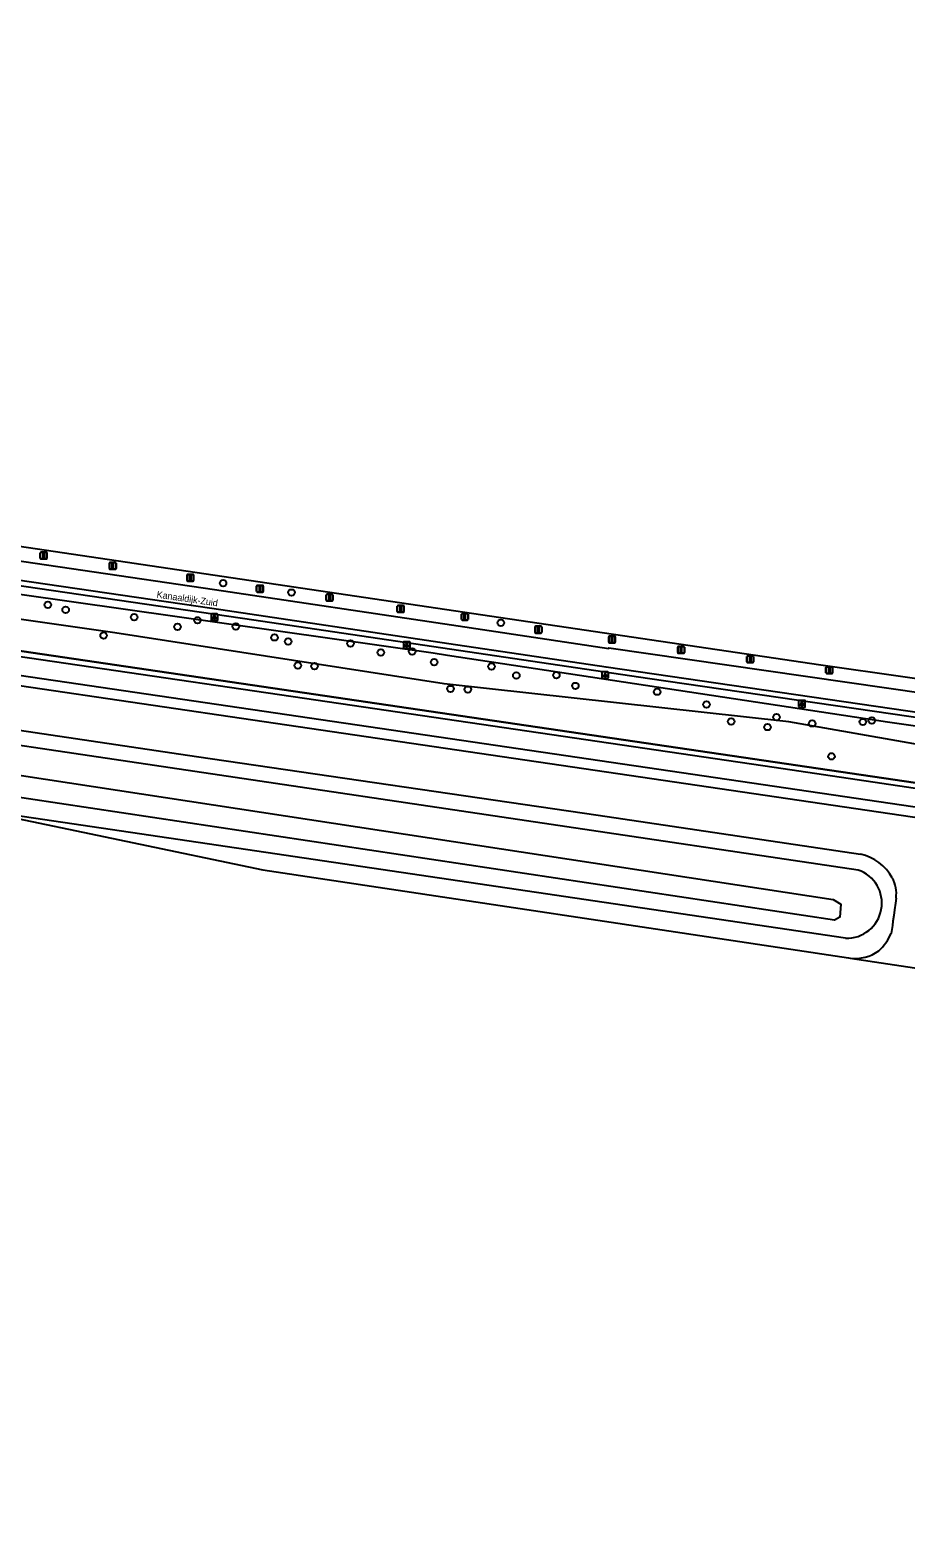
# Model space of a CAD drawing. Extents: x 163046 to 165074, y 382019 to 382874.
# Drawn here: x 163631.7 to 163762.7, y 382627.9 to 382853.5 of the extents above; entities that cross this region are included whole.
import ezdxf

# ---------------------------------------------------------------- set-up
doc = ezdxf.new("R2010")
doc.units = 0
for name, color, linetype in [('IMGEO_Afsluitpaal', 7, 'Continuous'), ('IMGEO_Boom', 7, 'Continuous'), ('IMGEO_Erf', 7, 'Continuous'), ('IMGEO_Fietspad_gesloten', 7, 'Continuous'), ('IMGEO_Groenvoorziening', 7, 'Continuous'), ('IMGEO_Hek', 7, 'Continuous'), ('IMGEO_Lichtpunt', 7, 'Continuous'), ('IMGEO_Openbare_ruimte_label', 7, 'Continuous'), ('IMGEO_Rijbaan_lokaal_gesloten', 7, 'Continuous'), ('IMGEO_Rijbaan_lokaal_halfverhard', 7, 'Continuous'), ('IMGEO_Waterloop', 7, 'Continuous')]:
    doc.layers.add(name, color=color, linetype=linetype)

msp = doc.modelspace()

# ---------------------------------------------------------------- linework, layer by layer
at = {"layer": 'IMGEO_Afsluitpaal'}
for p, q in [((163633.35, 382775.38), (163634.14, 382775.38)), ((163634.14, 382775.38), (163633.35, 382775.38)), ((163633.25, 382774.48), (163633.25, 382775.28)), ((163633.25, 382775.28), (163633.25, 382774.48)), ((163634.14, 382774.38), (163633.35, 382774.38)), ((163633.35, 382774.38), (163634.14, 382774.38)), ((163634.24, 382775.28), (163634.24, 382774.48)), ((163634.24, 382774.48), (163634.24, 382775.28)), ((163643.59, 382772.93), (163643.59, 382773.73)), ((163643.59, 382773.73), (163643.59, 382772.93)), ((163643.69, 382773.83), (163644.48, 382773.83)), ((163644.48, 382773.83), (163643.69, 382773.83)), ((163644.58, 382773.73), (163644.58, 382772.93)), ((163644.58, 382772.93), (163644.58, 382773.73)), ((163644.48, 382772.83), (163643.69, 382772.83)), ((163643.69, 382772.83), (163644.48, 382772.83)), ((163655.19, 382771.16), (163655.19, 382771.96)), ((163655.19, 382771.96), (163655.19, 382771.16)), ((163655.29, 382772.06), (163656.07, 382772.06)), ((163656.07, 382772.06), (163655.29, 382772.06)), ((163656.07, 382771.06), (163655.29, 382771.06)), ((163655.29, 382771.06), (163656.07, 382771.06)), ((163656.17, 382771.96), (163656.17, 382771.16)), ((163656.17, 382771.16), (163656.17, 382771.96)), ((163665.6, 382769.53), (163665.6, 382770.33)), ((163665.6, 382770.33), (163665.6, 382769.53)), ((163665.7, 382770.43), (163666.49, 382770.43)), ((163666.49, 382770.43), (163665.7, 382770.43)), ((163666.49, 382769.43), (163665.7, 382769.43)), ((163665.7, 382769.43), (163666.49, 382769.43)), ((163666.59, 382770.33), (163666.59, 382769.53)), ((163666.59, 382769.53), (163666.59, 382770.33)), ((163676.01, 382768.2), (163676.01, 382769)), ((163676.01, 382769), (163676.01, 382768.2)), ((163676.11, 382769.1), (163676.9, 382769.1)), ((163676.9, 382769.1), (163676.11, 382769.1)), ((163677, 382769), (163677, 382768.2)), ((163677, 382768.2), (163677, 382769)), ((163676.9, 382768.1), (163676.11, 382768.1)), ((163676.11, 382768.1), (163676.9, 382768.1)), ((163686.64, 382766.51), (163686.64, 382767.31)), ((163686.64, 382767.31), (163686.64, 382766.51)), ((163686.74, 382767.41), (163687.53, 382767.41)), ((163687.53, 382767.41), (163686.74, 382767.41)), ((163687.53, 382766.41), (163686.74, 382766.41)), ((163686.74, 382766.41), (163687.53, 382766.41)), ((163687.63, 382767.31), (163687.63, 382766.51)), ((163687.63, 382766.51), (163687.63, 382767.31)), ((163696.24, 382765.32), (163696.24, 382766.12)), ((163696.24, 382766.12), (163696.24, 382765.32)), ((163696.34, 382766.22), (163697.13, 382766.22)), ((163697.13, 382766.22), (163696.34, 382766.22)), ((163697.13, 382765.22), (163696.34, 382765.22)), ((163696.34, 382765.22), (163697.13, 382765.22)), ((163697.23, 382766.12), (163697.23, 382765.32)), ((163697.23, 382765.32), (163697.23, 382766.12)), ((163707.24, 382763.4), (163707.24, 382764.2)), ((163707.24, 382764.2), (163707.24, 382763.4)), ((163707.34, 382764.3), (163708.13, 382764.3)), ((163708.13, 382764.3), (163707.34, 382764.3)), ((163708.23, 382764.2), (163708.23, 382763.4)), ((163708.23, 382763.4), (163708.23, 382764.2)), ((163708.13, 382763.3), (163707.34, 382763.3)), ((163707.34, 382763.3), (163708.13, 382763.3)), ((163718.25, 382761.93), (163718.25, 382762.73)), ((163718.25, 382762.73), (163718.25, 382761.93)), ((163718.35, 382762.83), (163719.14, 382762.83)), ((163719.14, 382762.83), (163718.35, 382762.83)), ((163719.14, 382761.83), (163718.35, 382761.83)), ((163718.35, 382761.83), (163719.14, 382761.83)), ((163719.24, 382762.73), (163719.24, 382761.93)), ((163719.24, 382761.93), (163719.24, 382762.73)), ((163728.58, 382760.38), (163728.58, 382761.18)), ((163728.58, 382761.18), (163728.58, 382760.38)), ((163728.68, 382761.28), (163729.47, 382761.28)), ((163729.47, 382761.28), (163728.68, 382761.28)), ((163729.47, 382760.28), (163728.68, 382760.28)), ((163728.68, 382760.28), (163729.47, 382760.28)), ((163729.57, 382761.18), (163729.57, 382760.38)), ((163729.57, 382760.38), (163729.57, 382761.18)), ((163738.92, 382758.97), (163738.92, 382759.77)), ((163738.92, 382759.77), (163738.92, 382758.97)), ((163739.02, 382759.87), (163739.81, 382759.87)), ((163739.81, 382759.87), (163739.02, 382759.87)), ((163739.91, 382759.77), (163739.91, 382758.97)), ((163739.91, 382758.97), (163739.91, 382759.77)), ((163739.81, 382758.87), (163739.02, 382758.87)), ((163739.02, 382758.87), (163739.81, 382758.87)), ((163750.74, 382757.35), (163750.74, 382758.15)), ((163750.74, 382758.15), (163750.74, 382757.35)), ((163750.84, 382758.25), (163751.63, 382758.25)), ((163751.63, 382758.25), (163750.84, 382758.25)), ((163751.73, 382758.15), (163751.73, 382757.35)), ((163751.73, 382757.35), (163751.73, 382758.15)), ((163751.63, 382757.25), (163750.84, 382757.25)), ((163750.84, 382757.25), (163751.63, 382757.25))]:
    msp.add_line(p, q, dxfattribs=at)
for points in [[(163633.67, 382775.26), (163633.82, 382775.26), (163633.82, 382774.51), (163633.67, 382774.51), (163633.67, 382775.26)], [(163644.01, 382773.71), (163644.16, 382773.71), (163644.16, 382772.96), (163644.01, 382772.96), (163644.01, 382773.71)], [(163655.6, 382771.93), (163655.76, 382771.93), (163655.76, 382771.18), (163655.6, 382771.18), (163655.6, 382771.93)], [(163666.02, 382770.31), (163666.17, 382770.31), (163666.17, 382769.56), (163666.02, 382769.56), (163666.02, 382770.31)], [(163676.43, 382768.98), (163676.58, 382768.98), (163676.58, 382768.23), (163676.43, 382768.23), (163676.43, 382768.98)], [(163687.06, 382767.28), (163687.21, 382767.28), (163687.21, 382766.53), (163687.06, 382766.53), (163687.06, 382767.28)], [(163696.66, 382766.1), (163696.81, 382766.1), (163696.81, 382765.35), (163696.66, 382765.35), (163696.66, 382766.1)], [(163707.66, 382764.18), (163707.81, 382764.18), (163707.81, 382763.43), (163707.66, 382763.43), (163707.66, 382764.18)], [(163718.67, 382762.7), (163718.82, 382762.7), (163718.82, 382761.95), (163718.67, 382761.95), (163718.67, 382762.7)], [(163729, 382761.15), (163729.15, 382761.15), (163729.15, 382760.4), (163729, 382760.4), (163729, 382761.15)], [(163739.34, 382759.75), (163739.49, 382759.75), (163739.49, 382759), (163739.34, 382759), (163739.34, 382759.75)], [(163751.16, 382758.12), (163751.31, 382758.12), (163751.31, 382757.37), (163751.16, 382757.37), (163751.16, 382758.12)]]:
    msp.add_lwpolyline(points, dxfattribs=at)
for centre, start, end in [((163633.35, 382775.28), 90, 180), ((163633.35, 382775.28), 90, 180), ((163634.14, 382775.28), 0, 90), ((163634.14, 382775.28), 360, 90), ((163633.35, 382774.48), 180, 270), ((163633.35, 382774.48), 180, 270), ((163634.14, 382774.48), 270, 0), ((163634.14, 382774.48), 270, 0), ((163643.69, 382773.73), 90, 180), ((163643.69, 382773.73), 90, 180), ((163644.48, 382773.73), 0, 90), ((163644.48, 382773.73), 360, 90), ((163643.69, 382772.93), 180, 270), ((163643.69, 382772.93), 180, 270), ((163644.48, 382772.93), 270, 0), ((163644.48, 382772.93), 270, 0), ((163655.29, 382771.96), 90, 180), ((163655.29, 382771.96), 90, 180), ((163655.29, 382771.16), 180, 270), ((163655.29, 382771.16), 180, 270), ((163656.07, 382771.96), 0, 90), ((163656.07, 382771.96), 360, 90), ((163656.07, 382771.16), 270, 0), ((163656.07, 382771.16), 270, 0), ((163665.7, 382770.33), 90, 180), ((163665.7, 382770.33), 90, 180), ((163665.7, 382769.53), 180, 270), ((163665.7, 382769.53), 180, 270), ((163666.49, 382770.33), 0, 90), ((163666.49, 382770.33), 360, 90), ((163666.49, 382769.53), 270, 0), ((163666.49, 382769.53), 270, 0), ((163676.11, 382769), 90, 180), ((163676.11, 382769), 90, 180), ((163676.9, 382769), 0, 90), ((163676.9, 382769), 360, 90), ((163676.11, 382768.2), 180, 270), ((163676.11, 382768.2), 180, 270), ((163676.9, 382768.2), 270, 0), ((163676.9, 382768.2), 270, 0), ((163686.74, 382767.31), 90, 180), ((163686.74, 382767.31), 90, 180), ((163686.74, 382766.51), 180, 270), ((163686.74, 382766.51), 180, 270), ((163687.53, 382767.31), 0, 90), ((163687.53, 382767.31), 360, 90), ((163687.53, 382766.51), 270, 0), ((163687.53, 382766.51), 270, 0), ((163696.34, 382766.12), 90, 180), ((163696.34, 382766.12), 90, 180), ((163696.34, 382765.32), 180, 270), ((163696.34, 382765.32), 180, 270), ((163697.13, 382766.12), 0, 90), ((163697.13, 382766.12), 360, 90), ((163697.13, 382765.32), 270, 0), ((163697.13, 382765.32), 270, 0), ((163707.34, 382764.2), 90, 180), ((163707.34, 382764.2), 90, 180), ((163708.13, 382764.2), 0, 90), ((163708.13, 382764.2), 360, 90), ((163707.34, 382763.4), 180, 270), ((163707.34, 382763.4), 180, 270), ((163708.13, 382763.4), 270, 0), ((163708.13, 382763.4), 270, 0), ((163718.35, 382762.73), 90, 180), ((163718.35, 382762.73), 90, 180), ((163718.35, 382761.93), 180, 270), ((163718.35, 382761.93), 180, 270), ((163719.14, 382762.73), 0, 90), ((163719.14, 382762.73), 360, 90), ((163719.14, 382761.93), 270, 0), ((163719.14, 382761.93), 270, 0), ((163728.68, 382761.18), 90, 180), ((163728.68, 382761.18), 90, 180), ((163728.68, 382760.38), 180, 270), ((163728.68, 382760.38), 180, 270), ((163729.47, 382761.18), 0, 90), ((163729.47, 382761.18), 360, 90), ((163729.47, 382760.38), 270, 0), ((163729.47, 382760.38), 270, 0), ((163739.02, 382759.77), 90, 180), ((163739.02, 382759.77), 90, 180), ((163739.81, 382759.77), 0, 90), ((163739.81, 382759.77), 360, 90), ((163739.02, 382758.97), 180, 270), ((163739.02, 382758.97), 180, 270), ((163739.81, 382758.97), 270, 0), ((163739.81, 382758.97), 270, 0), ((163750.84, 382758.15), 90, 180), ((163750.84, 382758.15), 90, 180), ((163750.84, 382757.35), 180, 270), ((163750.84, 382757.35), 180, 270), ((163751.63, 382758.15), 0, 90), ((163751.63, 382758.15), 360, 90), ((163751.63, 382757.35), 270, 0), ((163751.63, 382757.35), 270, 0)]:
    msp.add_arc(centre, 0.1, start, end, dxfattribs=at)
at = {"layer": 'IMGEO_Boom'}
for centre in [(163660.58, 382770.77), (163670.83, 382769.34), (163634.37, 382767.52), (163637.04, 382766.76), (163647.27, 382765.67), (163653.78, 382764.22), (163656.75, 382765.2), (163662.49, 382764.27), (163702.12, 382764.82), (163642.72, 382762.93), (163668.26, 382762.65), (163670.33, 382762.04), (163679.63, 382761.73), (163684.18, 382760.39), (163688.87, 382760.53), (163671.77, 382758.43), (163674.25, 382758.35), (163692.14, 382758.93), (163700.73, 382758.28), (163704.44, 382756.94), (163710.43, 382757), (163694.61, 382754.93), (163697.2, 382754.83), (163713.27, 382755.38), (163725.5, 382754.52), (163732.89, 382752.62), (163736.56, 382750.05), (163743.36, 382750.71), (163757.61, 382750.2), (163742, 382749.23), (163748.69, 382749.78), (163756.25, 382749.99), (163751.58, 382744.85)]:
    msp.add_circle(centre, 0.489, dxfattribs=at)
at = {"layer": 'IMGEO_Erf'}
for points in [[(163551.71, 382756.34), (163551.82, 382757.15), (163552.77, 382757.02), (163552.78, 382757.12), (163555.08, 382756.83), (163555.19, 382757.61), (163606.71, 382750), (163755.55, 382727.85)], [(163753.68, 382717.65), (163616.32, 382737.96), (163609.51, 382732.91), (163594.68, 382735.09), (163589.61, 382741.91), (163553.67, 382747.12), (163553.28, 382747.47), (163553.16, 382746.69)], [(163589.84, 382629.98), (163598.25, 382663.73), (163605.6, 382662.09), (163616.25, 382704.79), (163625.48, 382736.46), (163666.55, 382727.85), (163754.11, 382714.7), (163754.37, 382714.66)]]:
    msp.add_lwpolyline(points, dxfattribs=at)
msp.add_arc((163753.87, 382722.88), 5.24, 267.9484, 71.35, dxfattribs=at)
at = {"layer": 'IMGEO_Fietspad_gesloten'}
for points in [[(163262.2, 382833.43), (163314.79, 382823.48), (163323.12, 382821.97), (163364.34, 382814.88), (163364.32, 382814.73), (163391.13, 382810.02), (163404.12, 382807.82), (163422.79, 382804.65), (163452.38, 382800.08), (163452.39, 382800.23), (163481.75, 382795.75), (163600.16, 382778.49), (163659.31, 382769.79), (163694.75, 382764.5), (163718.27, 382760.99), (163718.28, 382761.09), (163777.46, 382752.55), (163894.24, 382735.48), (163935.71, 382729.35)], [(164290.62, 382661.73), (164274.25, 382664.12), (164260.42, 382666.24), (164243.89, 382668.69), (164144.23, 382683.65), (164123, 382686.71), (164101.01, 382689.99), (164076.37, 382693.78), (164055.27, 382696.95), (164027.35, 382701.08), (164001.81, 382704.9), (163972.99, 382709.21), (163941.3, 382713.95), (163899.36, 382720.17), (163864.59, 382725.29), (163853.75, 382726.93), (163828.34, 382730.66), (163782.57, 382737.3), (163742.98, 382743.16), (163672.74, 382753.5), (163608.81, 382762.9), (163587.4, 382766.11), (163537.53, 382773.31), (163534.17, 382773.83)], [(163557.09, 382767.74), (163843.81, 382725.57)]]:
    msp.add_lwpolyline(points, dxfattribs=at)
at = {"layer": 'IMGEO_Groenvoorziening'}
msp.add_lwpolyline([(163359.37, 382797.83), (163374.85, 382798.03), (163401.89, 382794.15), (163410.94, 382792.85), (163500, 382779.47), (163535.41, 382774.6), (163550.62, 382772.33), (163693.06, 382751.36), (163828.8, 382731.36), (163846.1, 382728.88), (163873.33, 382724.84), (163916.5, 382718.52), (163943.51, 382714.37), (163981.6, 382708.67), (164080.42, 382694.02), (164103.91, 382690.52), (164197.42, 382676.27), (164217.65, 382673.07), (164282.56, 382663.33), (164518.36, 382627.93)], dxfattribs=at)
at = {"layer": 'IMGEO_Hek'}
for points in [[(163693.06, 382751.36), (163550.62, 382772.33), (163535.41, 382774.6)], [(163981.6, 382708.67), (163943.51, 382714.37), (163916.5, 382718.52), (163873.33, 382724.84), (163846.1, 382728.88), (163828.8, 382731.36), (163693.06, 382751.36)]]:
    msp.add_lwpolyline(points, dxfattribs=at)
at = {"layer": 'IMGEO_Lichtpunt'}
for p, q in [((163658.78, 382766.05), (163658.78, 382765.25)), ((163658.78, 382766.05), (163658.78, 382765.25)), ((163659.68, 382766.15), (163658.88, 382766.15)), ((163659.68, 382766.15), (163658.88, 382766.15)), ((163658.88, 382765.15), (163659.68, 382765.15)), ((163658.88, 382765.15), (163659.68, 382765.15)), ((163659.78, 382765.25), (163659.78, 382766.05)), ((163659.78, 382765.25), (163659.78, 382766.05)), ((163687.56, 382761.89), (163687.56, 382761.09)), ((163687.56, 382761.89), (163687.56, 382761.09)), ((163688.46, 382761.99), (163687.65, 382761.99)), ((163688.46, 382761.99), (163687.65, 382761.99)), ((163688.56, 382761.09), (163688.56, 382761.89)), ((163688.56, 382761.09), (163688.56, 382761.89)), ((163687.65, 382760.99), (163688.46, 382760.99)), ((163687.65, 382760.99), (163688.46, 382760.99)), ((163717.23, 382757.4), (163717.23, 382756.59)), ((163717.23, 382757.4), (163717.23, 382756.59)), ((163718.13, 382757.49), (163717.33, 382757.49)), ((163718.13, 382757.49), (163717.33, 382757.49)), ((163718.23, 382756.59), (163718.23, 382757.4)), ((163718.23, 382756.59), (163718.23, 382757.4)), ((163717.33, 382756.49), (163718.13, 382756.49)), ((163717.33, 382756.49), (163718.13, 382756.49)), ((163746.65, 382753.12), (163746.65, 382752.31)), ((163746.65, 382753.12), (163746.65, 382752.31)), ((163747.55, 382753.22), (163746.74, 382753.22)), ((163747.55, 382753.22), (163746.74, 382753.22)), ((163747.65, 382752.31), (163747.65, 382753.12)), ((163747.65, 382752.31), (163747.65, 382753.12)), ((163746.74, 382752.22), (163747.55, 382752.22)), ((163746.74, 382752.22), (163747.55, 382752.22))]:
    msp.add_line(p, q, dxfattribs=at)
for points in [[(163659.16, 382765.72), (163659.2, 382765.69), (163659.01, 382765.43), (163658.97, 382765.45), (163659.16, 382765.72)], [(163659.26, 382765.67), (163659.31, 382765.67), (163659.31, 382765.35), (163659.26, 382765.35), (163659.26, 382765.67)], [(163659.37, 382765.69), (163659.41, 382765.72), (163659.59, 382765.45), (163659.56, 382765.43), (163659.37, 382765.69)], [(163687.93, 382761.56), (163687.97, 382761.53), (163687.78, 382761.27), (163687.75, 382761.29), (163687.93, 382761.56)], [(163688.03, 382761.51), (163688.08, 382761.51), (163688.08, 382761.19), (163688.03, 382761.19), (163688.03, 382761.51)], [(163688.14, 382761.53), (163688.18, 382761.56), (163688.37, 382761.29), (163688.33, 382761.27), (163688.14, 382761.53)], [(163717.61, 382757.06), (163717.64, 382757.03), (163717.46, 382756.77), (163717.42, 382756.8), (163717.61, 382757.06)], [(163717.71, 382757.01), (163717.76, 382757.01), (163717.76, 382756.69), (163717.71, 382756.69), (163717.71, 382757.01)], [(163717.82, 382757.03), (163717.86, 382757.06), (163718.04, 382756.8), (163718, 382756.77), (163717.82, 382757.03)], [(163747.02, 382752.78), (163747.06, 382752.76), (163746.87, 382752.49), (163746.84, 382752.52), (163747.02, 382752.78)], [(163747.23, 382752.76), (163747.27, 382752.78), (163747.46, 382752.52), (163747.42, 382752.49), (163747.23, 382752.76)], [(163747.12, 382752.74), (163747.17, 382752.74), (163747.17, 382752.41), (163747.12, 382752.41), (163747.12, 382752.74)]]:
    msp.add_lwpolyline(points, dxfattribs=at)
for centre in [(163659.28, 382765.85), (163688.06, 382761.69), (163717.73, 382757.19), (163747.15, 382752.92)]:
    msp.add_circle(centre, 0.0994, dxfattribs=at)
for centre, start, end in [((163658.88, 382766.05), 90, 180), ((163658.88, 382766.05), 90, 180), ((163658.88, 382765.25), 180, 270), ((163658.88, 382765.25), 180, 270), ((163659.68, 382766.05), 0, 90), ((163659.68, 382766.05), 0, 90), ((163659.68, 382765.25), 270, 0), ((163659.68, 382765.25), 270, 360), ((163687.65, 382761.89), 90, 180), ((163687.65, 382761.89), 90, 180), ((163688.46, 382761.89), 0, 90), ((163688.46, 382761.89), 0, 90), ((163687.65, 382761.09), 180, 270), ((163687.65, 382761.09), 180, 270), ((163688.46, 382761.09), 270, 0), ((163688.46, 382761.09), 270, 360), ((163717.33, 382757.4), 90, 180), ((163717.33, 382757.4), 90, 180), ((163718.13, 382757.4), 0, 90), ((163718.13, 382757.4), 0, 90), ((163717.33, 382756.59), 180, 270), ((163717.33, 382756.59), 180, 270), ((163718.13, 382756.59), 270, 0), ((163718.13, 382756.59), 270, 360), ((163746.74, 382753.12), 90, 180), ((163746.74, 382753.12), 90, 180), ((163747.55, 382753.12), 0, 90), ((163747.55, 382753.12), 0, 90), ((163746.74, 382752.31), 180, 270), ((163746.74, 382752.31), 180, 270), ((163747.55, 382752.31), 270, 0), ((163747.55, 382752.31), 270, 360)]:
    msp.add_arc(centre, 0.0946, start, end, dxfattribs=at)
at = {"layer": 'IMGEO_Rijbaan_lokaal_gesloten'}
for points in [[(163843.6, 382723.98), (163831.84, 382725.71), (163666.72, 382750), (163556.9, 382766.15)], [(163555.64, 382759.8), (163592.57, 382754.34), (163656.59, 382744.84), (163716.68, 382736.05), (163755.9, 382730.2)], [(163761.24, 382723.64), (163761.15, 382722.89), (163761.01, 382721.91), (163760.89, 382721.05), (163760.77, 382720.2), (163760.7, 382719.56), (163760.49, 382718.36)], [(163754.37, 382714.66), (163779.91, 382710.83)]]:
    msp.add_lwpolyline(points, dxfattribs=at)
for centre, radius, start, end in [((163754.55, 382723.46), 6.88, 27.6255, 78.7043), ((163756.67, 382724.31), 4.61, 351.7137, 30.4658), ((163753.32, 382721.49), 7.83, 312.818, 336.3817), ((163755.13, 382720.59), 5.98, 262.7775, 305.9827)]:
    msp.add_arc(centre, radius, start, end, dxfattribs=at)
at = {"layer": 'IMGEO_Rijbaan_lokaal_halfverhard'}
for points in [[(163935.2, 382726.45), (163865.22, 382736.76), (163777.02, 382749.58), (163717.86, 382758.17), (163694.37, 382761.68), (163658.89, 382766.97), (163481.33, 382792.88), (163422.35, 382801.94), (163403.68, 382805.1), (163390.65, 382807.22), (163363.84, 382811.92), (163322.62, 382819.12), (163314.27, 382820.6), (163290.92, 382824.68), (163261.84, 382830.05)], [(163322.47, 382818.43), (163367.47, 382810.55), (163392.06, 382806.33), (163416.38, 382802.09), (163437.86, 382798.77), (163477.86, 382792.74), (163535.08, 382784.39), (163586.49, 382776.8), (163665.19, 382765.27), (163724.04, 382756.55), (163797.09, 382745.94), (163942.52, 382724.63), (163982.95, 382718.82), (164038.68, 382710.5), (164106.21, 382700.45), (164167.93, 382691.09), (164227.93, 382681.9), (164243.96, 382679.59)]]:
    msp.add_lwpolyline(points, dxfattribs=at)
at = {"layer": 'IMGEO_Waterloop'}
for points in [[(163181.62, 382853.49), (163197.03, 382850.28), (163305.26, 382829.6), (163305.57, 382830.01), (163310.04, 382829.2), (163310.24, 382828.46), (163351.91, 382819.96), (163378.29, 382814.85), (163404.52, 382810.31), (163423.67, 382806.99), (163441.72, 382804), (163484.72, 382798.05), (163500, 382795.74), (163550.36, 382788.13), (163695.04, 382766.67), (163750, 382758.53), (163787.83, 382753.17), (163808.82, 382750), (163842.64, 382744.9), (163893.44, 382737.78), (163957.08, 382728.48), (163984.26, 382724.67)], [(163960.72, 382718.96), (163901.57, 382725.6), (163891.58, 382726.84), (163814.14, 382738.31), (163792.78, 382741.61), (163745.19, 382750), (163693.63, 382755.7), (163644.4, 382763.31), (163599.03, 382769.82), (163550.48, 382777.74), (163531.31, 382780.73), (163500, 382785.31), (163403.56, 382799.39), (163402.77, 382799.54), (163335.61, 382812.21), (163322.88, 382814.5)], [(163337.61, 382814.84), (163359.3, 382810.82), (163403.34, 382803.03), (163422.96, 382799.57), (163500, 382787.56), (163548.66, 382779.98), (163558.31, 382778.65), (163599.59, 382773.47), (163692, 382760.32), (163694.14, 382759.99), (163759.96, 382750), (163780.57, 382747.06), (163793.38, 382745.36), (163843.66, 382737.95), (163892.47, 382731.14), (163941.47, 382723.93), (163961.29, 382721.23)], [(163550.24, 382753.72), (163551.31, 382753.63), (163551.87, 382753.58), (163554.57, 382753.35), (163556.34, 382753.2), (163562.84, 382752.3), (163751.82, 382723.43), (163752.98, 382722.72), (163752.82, 382720.79), (163752.03, 382720.32), (163612.9, 382741.27), (163607.89, 382736.86), (163595.91, 382738.22), (163590.56, 382745.01), (163555.74, 382750.53)]]:
    msp.add_lwpolyline(points, dxfattribs=at)

# ---------------------------------------------------------------- texts
at = {"layer": 'IMGEO_Openbare_ruimte_label'}
msp.add_text('Kanaaldijk-Zuid', height=1, rotation=351.6591, dxfattribs=at).set_placement((163650.6, 382768.61))

doc.saveas('drawing.dxf')
